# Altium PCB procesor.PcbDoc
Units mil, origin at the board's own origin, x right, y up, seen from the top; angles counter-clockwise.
Board outline 6000 x 4000 mil, 2 copper layers (Top Layer, Bottom Layer); 49 components, 70 nets, 266 pads, 119 vias.
Unrouted connection lines stored in the file: 1.
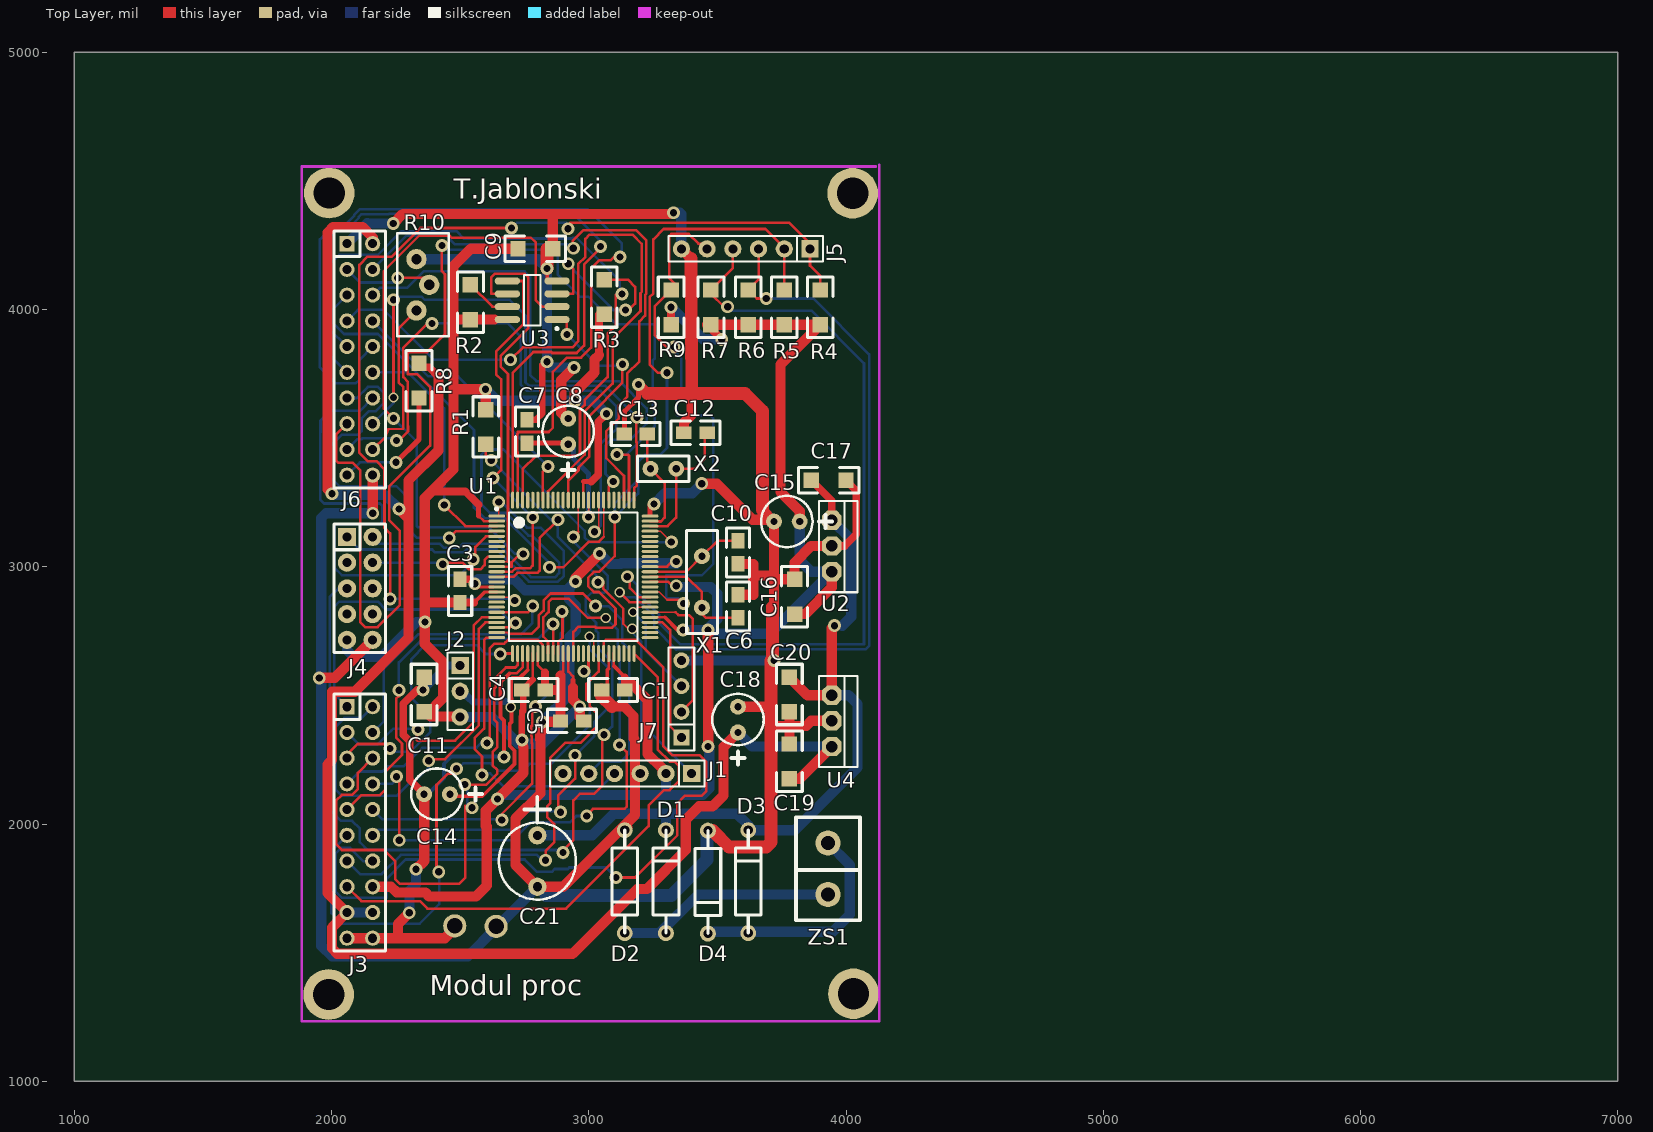
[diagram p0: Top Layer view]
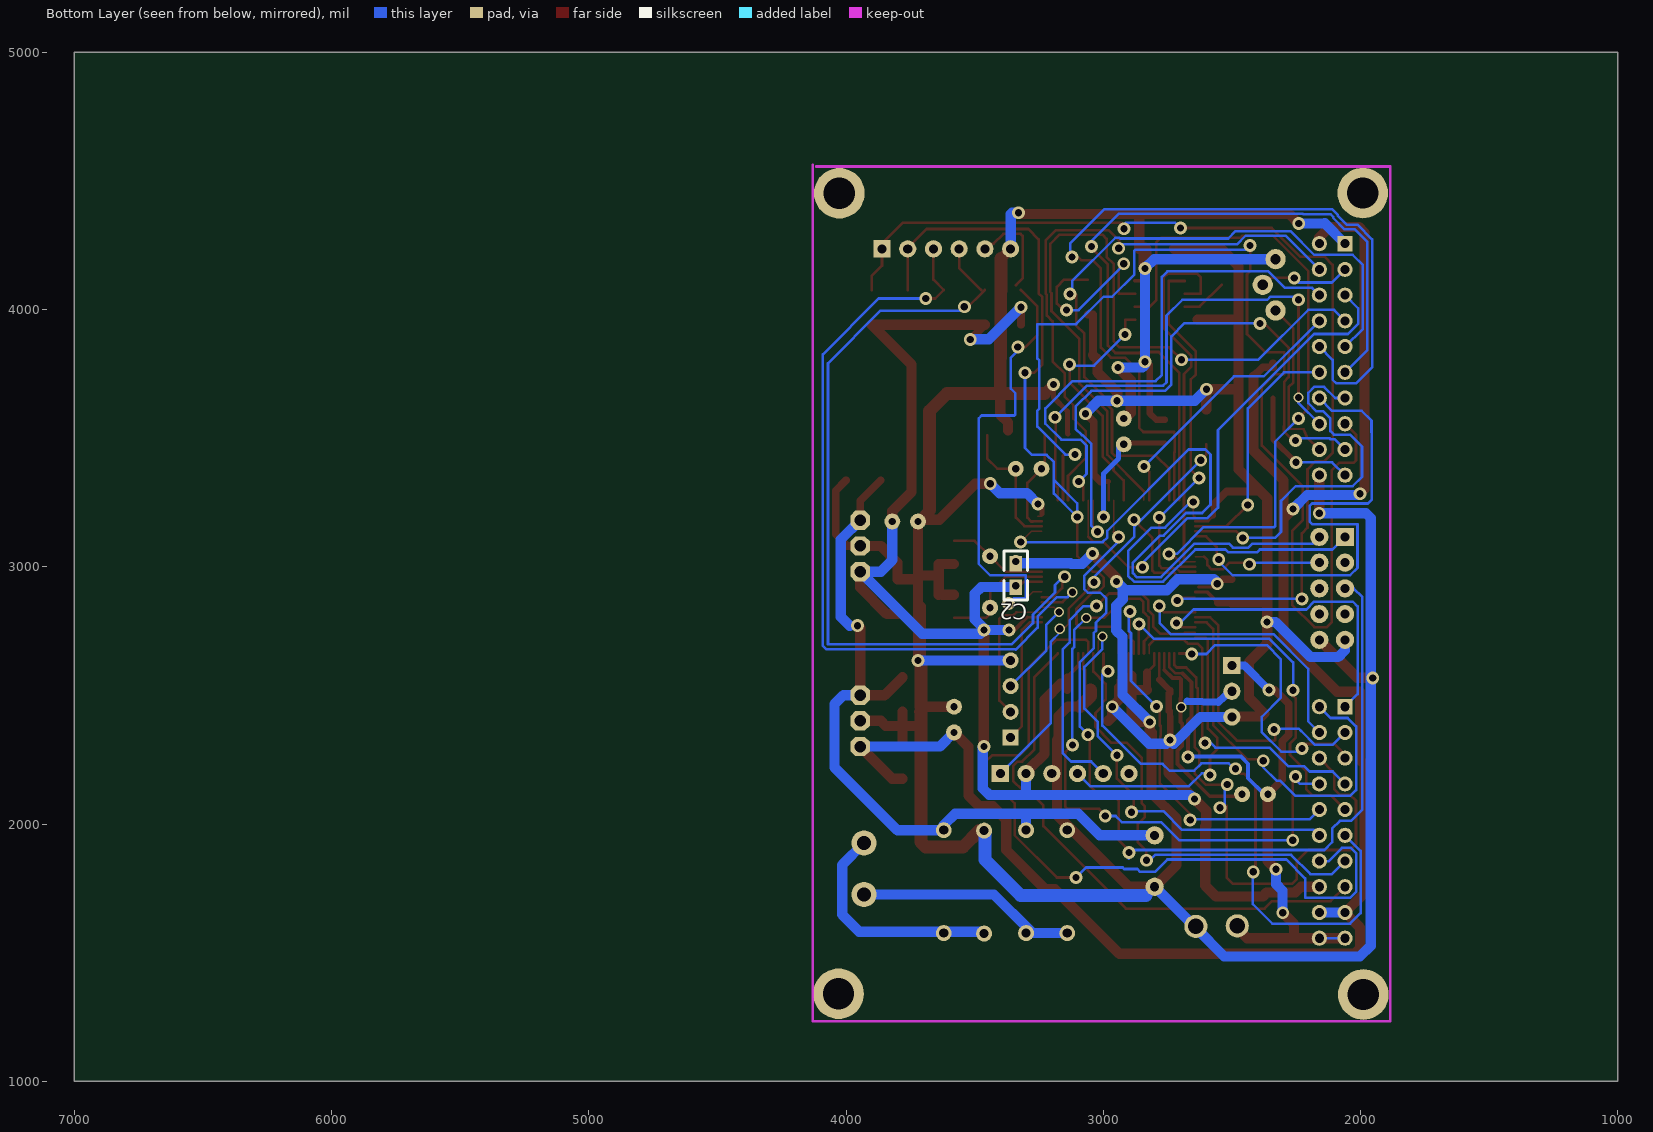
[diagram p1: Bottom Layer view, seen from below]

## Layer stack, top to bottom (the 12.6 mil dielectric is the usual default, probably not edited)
Top Layer: signal copper 1.4
Dielectric: dielectric 12.6, FR-4, Dk 4.8
Bottom Layer: signal copper 1.4

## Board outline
1000,1000 7000,1000 7000,5000 1000,5000

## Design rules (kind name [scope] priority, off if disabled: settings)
Clearance [All] p1: gap=8
PolygonConnect [All] p1: connectstyle=Relief reliefconductorwidth=10 reliefentries=4 polygonreliefangle="90 Angle"
RoomDefinition procesor [InComponentClass('procesor')] p1: confinementstyle=ConfineIn formatcopy=TRUE lockcomponents=FALSE outline 0,0 2000,0 2000,1000 0,1000
RoutingTopology [All] p1: topology=Starburst
RoutingVias [All] p1: holewidth=28 width=50 viastyle="Through Hole" minholewidth=28 minwidth=50 maxholewidth=28 maxwidth=50
SMDNeckDown [All] p1: percent=50.000
SilkscreenOverComponentPads [All] p1: minsilkscreentomaskgap=10
SolderMaskExpansion [All] p1: expansion=4
Width +3,3V [InNet('+3,3V')] p1: maxlimit=40 minlimit=40 preferedwidth=40
Width GND [InNet('GND')] p2: maxlimit=40 minlimit=40 preferedwidth=40
Width +5V [InNet('+5V')] p3: maxlimit=40 minlimit=40 preferedwidth=40
Width ALL [All] p4: maxlimit=10 minlimit=10 preferedwidth=10
26 further rules are at their usual default settings.

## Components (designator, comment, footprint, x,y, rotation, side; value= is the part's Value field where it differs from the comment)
C1 "100n" 0805 3140,2521 r180 top
C2 "100n" 0805 3340,2921 r90 bottom
C3 "100n" 0805 2500,2861 r90 top
C4 "100n" 0805 2740,2521 r0 top
C5 "100n" 0805 2980,2401 r180 top
C6 "22p" 0805 3580,2801 r90 top
C7 "100n" 0805 2760,3481 r90 top
C8 "10u" RB.1/.2 2920,3376 r270 top
C9 "100n" 1206 2860,4236 r180 top
C10 "22p" 0805 3580,3101 r270 top
C11 "100n" 1206 2360,2436 r90 top
C12 "22p" 0805 3460,3521 r180 top
C13 "22p" 0805 3227.29,3516.29 r180 top
C14 "10u" RB.1/.2 2560,2116 r0 top
C15 "10u" RB.1/.2 3920,3176 r0 top
C16 "100n" 1206 3800,2816 r90 top
C17 "100n" 1206 4000,3336 r180 top
C18 "10u" RB.1/.2 3580,2256 r270 top
C19 "100n" 1206 3780,2176 r90 top
C20 "100n" 1206 3780,2436 r90 top
C21 "1000u" RB.2/.3 2800,1956 r270 top
D1 "" DIODE0.4 3300,1576 r90 top
D2 "" DIODE0.4 3140,1976 r270 top
D3 "" DIODE0.4 3620,1576 r90 top
D4 "" DIODE0.4 3463.19,1974.15 r270 top
J1 "ICSP" SIP6 3400,2196 r180 top
J2 "CON3" SIP3 2500,2616 r270 top
J3 "analog" IDC20 2060,2456 r270 top
J4 "SD" IDC10 2060,3116 r270 top
J5 "CON6" SIP6 3860,4236 r180 top
J6 "lcd" IDC20 2060,4256 r270 top
J7 "CON4" SIP4 3360,2336 r90 top
R1 "4K7" 1206 2600,3476 r90 top
R2 "2k2" 1206 2540,4096 r270 top
R3 "2k2" 1206 3060,4116 r270 top
R4 "4K7" 1206 3900,4076 r270 top
R5 "4K7" 1206 3760,4076 r270 top
R6 "4K7" 1206 3620,4076 r270 top
R7 "4K7" 1206 3475,4076 r270 top
R8 "0R" 1206 2340,3656 r90 top
R9 "4K7" 1206 3320,4076 r270 top
R10 "RPot" PR 2380,4096 r90 top
U1 "PIC32MX795F512L-80I/PT" TQFP100 2940,2961 r0 top
U2 "LM2937" 78XXST 3960,3156 r270 top
U3 "25LC256-I/SN" SOIC127P600-8M 2780,4036 r180 top
U4 "LM2937" 78XXST 3960,2476 r270 top
X1 "8MHz" XTAL1 3440,2841 r90 top
X2 "8MHz" RAD0.1 3340,3381 r180 top
ZS1 "" ZLSRUB2-1 3960,1796 r90 top

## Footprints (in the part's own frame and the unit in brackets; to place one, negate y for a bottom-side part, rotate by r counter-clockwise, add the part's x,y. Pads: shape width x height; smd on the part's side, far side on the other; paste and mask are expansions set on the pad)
78XXST [mil]
  oct 75x75 hole 45: 1(-25,-15) 2(75,-15) 3(175,-15)
  silkscreen extent -100,-65 255,85
0805 [mil]
  rect 60x50 smd: 1(0,0) 2(90,0)
  silkscreen extent -50,-45 140,45
1206 [mil]
  rect 60x60 smd: 1(0,0) 2(135,0)
  silkscreen extent -50,-50 185,50
DIODE0.4 [mil]
  round 62 hole 35.43: A(0,0) K(400,0)
  silkscreen extent 0,-50 400,50
IDC10 [mm]
  rect 1.8x1.8 hole 0.9: 1(0,0)
  round 1.8 hole 0.9: 2(0,2.54) 3(2.54,0) 4(2.54,2.54) 5(5.08,0) 6(5.08,2.54) 7(7.62,0) 8(7.62,2.54) 9(10.16,0) 10(10.16,2.54)
  silkscreen extent -1.27,-1.27 11.43,3.81
IDC20 [mm]
  rect 1.5x1.5 hole 0.9: 1(0,0)
  round 1.5 hole 0.9: 2(0,2.54) 3(2.54,0) 4(2.54,2.54) 5(5.08,0) 6(5.08,2.54) 7(7.62,0) 8(7.62,2.54) 9(10.16,0) 10(10.16,2.54) 11(12.7,0) 12(12.7,2.54) 13(15.24,0) 14(15.24,2.54) 15(17.78,0) 16(17.78,2.54) 17(20.32,0) 18(20.32,2.54) 19(22.86,0) 20(22.86,2.54)
  silkscreen extent -1.27,-1.27 24.13,3.81
PR [mil]
  round 79 hole 40: 1(-100,50) 2(100,50) 3(0,0)
  silkscreen extent -200,-75 200,125
RAD0.1 [mil]
  round 62 hole 28: 1(0,0) 2(100,0)
  silkscreen extent -50,-50 150,50
RB.1/.2 [mil]
  round 62 hole 28: 1(-100,0) 2(-200,0)
  silkscreen extent -250,-100 25,100
RB.2/.3 [mm]
  round 1.8 hole 0.9: 1(0,0) 2(5.08,0)
  silkscreen extent -3.81,-3.81 6.35,3.81
SIP3 [mm]
  rect 1.7x1.7 hole 0.9: 1(0,0)
  round 1.7 hole 0.9: 2(2.54,0) 3(5.08,0)
  silkscreen extent -1.27,-1.27 6.35,1.27
SIP4 [mil]
  rect 62x62 hole 35.43: 1(0,0)
  round 62 hole 35.43: 2(100,0) 3(200,0) 4(300,0)
  silkscreen extent -50,-50 350,50
SIP6 [mm]
  rect 1.7x1.7 hole 0.9: 1(0,0)
  round 1.7 hole 0.9: 2(2.54,0) 3(5.08,0) 4(7.62,0) 5(10.16,0) 6(12.7,0)
  silkscreen extent -1.27,-1.27 13.97,1.27
SOIC127P600-8M [mm] "SOIC, 8-Leads, Body 4.9x3.9mm, Pitch 1.27mm, IPC Low Density"
  oval 2.5x0.7 smd: 1(-2.45,1.905) 2(-2.45,0.635) 3(-2.45,-0.635) 4(-2.45,-1.905) 5(2.45,-1.905) 6(2.45,-0.635) 7(2.45,0.635) 8(2.45,1.905)
  silkscreen extent -2.58,-2.5 0.8,2.93, body extent -2,-2.5 2,2.5, height 1.75
TQFP100 [mm]
  oval 1.65x0.3 smd: 1(-7.575,6) 2(-7.575,5.5) 3(-7.575,5) 4(-7.575,4.5) 5(-7.575,4) 6(-7.575,3.5) 7(-7.575,3) 8(-7.575,2.5) 9(-7.575,2) 10(-7.575,1.5) 11(-7.575,1) 12(-7.575,0.5) 13(-7.575,0) 14(-7.575,-0.5) 15(-7.575,-1) 16(-7.575,-1.5) 17(-7.575,-2) 18(-7.575,-2.5) 19(-7.575,-3) 20(-7.575,-3.5) 21(-7.575,-4) 22(-7.575,-4.5) 23(-7.575,-5) 24(-7.575,-5.5) 25(-7.575,-6) 51(7.575,-6) 52(7.575,-5.5) 53(7.575,-5) 54(7.575,-4.5) 55(7.575,-4) 56(7.575,-3.5) 57(7.575,-3) 58(7.575,-2.5) 59(7.575,-2) 60(7.575,-1.5) 61(7.575,-1) 62(7.575,-0.5) 63(7.575,0) 64(7.575,0.5) 65(7.575,1) 66(7.575,1.5) 67(7.575,2) 68(7.575,2.5) 69(7.575,3) 70(7.575,3.5) 71(7.575,4) 72(7.575,4.5) 73(7.575,5) 74(7.575,5.5) 75(7.575,6)
  oval 0.3x1.65 smd: 26(-6,-7.575) 27(-5.5,-7.575) 28(-5,-7.575) 29(-4.5,-7.575) 30(-4,-7.575) 31(-3.5,-7.575) 32(-3,-7.575) 33(-2.5,-7.575) 34(-2,-7.575) 35(-1.5,-7.575) 36(-1,-7.575) 37(-0.5,-7.575) 38(0,-7.575) 39(0.5,-7.575) 40(1,-7.575) 41(1.5,-7.575) 42(2,-7.575) 43(2.5,-7.575) 44(3,-7.575) 45(3.5,-7.575) 46(4,-7.575) 47(4.5,-7.575) 48(5,-7.575) 49(5.5,-7.575) 50(6,-7.575) 76(6,7.575) 77(5.5,7.575) 78(5,7.575) 79(4.5,7.575) 80(4,7.575) 81(3.5,7.575) 82(3,7.575) 83(2.5,7.575) 84(2,7.575) 85(1.5,7.575) 86(1,7.575) 87(0.5,7.575) 88(0,7.575) 89(-0.5,7.575) 90(-1,7.575) 91(-1.5,7.575) 92(-2,7.575) 93(-2.5,7.575) 94(-3,7.575) 95(-3.5,7.575) 96(-4,7.575) 97(-4.5,7.575) 98(-5,7.575) 99(-5.5,7.575) 100(-6,7.575)
  silkscreen extent -7.7,-6.35 6.35,6.82, body extent -7,-7 7,7, height 1.2
XTAL1 [mil]
  round 62 hole 28: 1(0,0) 2(200,0)
  silkscreen extent -100,-60 300,60
ZLSRUB2-1 [mil]
  round 98 hole 55: 1(-70,30) 2(130,30)
  silkscreen extent -170,-95 230,155

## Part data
C1 C2 C3 C4 C5 C6 C7 C10 C11 C12 C13 C16 C17 C19 C20: library part CAP, "Capacitor"
C8 C14 C15 C18 C21: library part ELECTRO2, "Electrolytic Capacitor"
C9: library part Cap, "Capacitor"
D1 D2 D3 D4: library part DIODE, "Diode"
J1: library part CON6, "Connector"
J2 J5 J7: "Connector"
J3 J6: library part 20PIN
J4: library part CON10, "Connector"
R1 R4 R5 R6 R7 R8 R9: library part RES2
R2 R3: library part Res2, "Resistor"
R10: "Potentiometer"
U1: "32-Bit Flash Microcontroller with USB, 85 IOs, 256KB Program Memory, 100-pin TQFP"
U2 U4: library part 78XX
U3: "256K SPI Bus Serial EEPROM, 8-Pin SOIC, Industrial Temperature"
X1 X2: library part CRYSTAL, "Crystal"
ZS1: library part ZLSRUB

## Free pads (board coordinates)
  round 90 hole 60: 0(2479,1604) 0(2640,1602)
  round 196.85 hole 122.05: 0(4029,1340) 1(1989,1337) 2(4026,4452) 3(1991,4453)

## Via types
v1: diameter 50, hole 28, Top Layer to Bottom Layer, 112 vias
v2: diameter 40, hole 28, Top Layer to Bottom Layer, 7 vias

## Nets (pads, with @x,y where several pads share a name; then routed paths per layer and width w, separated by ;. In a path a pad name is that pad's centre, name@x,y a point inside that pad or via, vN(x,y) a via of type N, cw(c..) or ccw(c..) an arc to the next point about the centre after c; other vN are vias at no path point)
+3,3V: C1.1 C2.1 C3.1 C4.1 C5.1 C9.2 C11.1 C15.1 C16.1 J1.2 J2.3 J3.16 J4.9 R1.2 R2.2 R3.2 R4.2 R5.2 R6.2 R7.2 R9.2 U1.2 U1.16 U1.30 U1.37 U1.46 U1.55 U1.62 U1.86 U2.3 U3.8 | length 13055.7
  Top Layer w5.91: 2555,2861 2595,2901 2595.94,2901.94 ; U1.46 3097.48,2614 3165.24,2546.24
  Top Layer w10: 2572,3198 2592.46,3177.54 U1.2 ; 2595.94,2901.94 U1.16 ; 2782.52,2561.52 U1.30 ; U1.37 2920.32,2592.35 2939,2573.67 2939,2560 ; U1.86 2979.37,3331 ; 3097.48,2613.52 U1.46 ; U1.55 3295.65,2803.52 ; U1.62 3309.69,2941.31 v1@3340,2911
  Top Layer w15: 2555,2861 2595,2901 ; 3097.48,2613.52 3140,2571 ; 3295.65,2803.52 v1@3345.17,2754
  Top Layer w20: 2572,3198 2572,3241 ; 2939,2530 2939,2560 ; 2979.37,3331 3010,3331
  Top Layer w25: v1@2740,2317.11 v1(2740,2326) 2740,2417.5 ; C4.1 2740,2508.5 2744.62,2508.5 2744.62,2437.7 ; 2740.5,2417.5 2740.5,2437.7 ; C4.1@2751,2530 2782.52,2561.52
  Top Layer w30: 2389,3293 2520,3293 2572,3241 ; C3.1 2555,2861 ; 3010,3331 3037,3358 3037,3563 v1@3064,3590 ; 3040,3823 3040,3981 R3.2 ; C1.1 3140,2571 ; R9.2 v1(3320,4009) ; R7.2@3460,3941 3467.5,3933.5 v1(3517,3884) ; C16.1@3799,2815 C16.1
  Top Layer w40: J3.16 2231.33,1756 2253.33,1734 2364,1734 2380,1718 2561,1718 2603.52,1760.52 2603.52,1989 2600,1992.52 2600,2052 v1(2645,2097) 2746.5,2198.5 2746.5,2299.7 2744,2302.2 v1@2744,2303.67 ; 2365,2861 C3.1 ; 2475,3961 R2.2 2633,3961 ; 2477,3690 v1(2599,3690) 2599,3612 R1.2 ; J2.3@2492,2418 2385,2418 2373.5,2429.5 2433,2489 2433,2630 2362,2701 2362,2785 2362,3266 2389,3293 2474,3378 2474,4168 2542,4236 C9.2 ; 2939,2530 2939,2482 v1(2965,2456) 2965,2416 C5.1 ; v1(2946,3645) 2946,3679 3022,3755 3022,3805 3040,3823 ; v1@3064,3590 v1(3069,3595) ; 3165.24,2546.24 3228,2483.48 3228,2273 3286.93,2214.07 J1.2@3286.93,2196 ; R7.2@3460,3941 R7.2 R6.2 R5.2 R4.2 3745,3786 3745,3291 3820,3216 C15.1 ; 3462,2711 3462,2754 v1@3462,2756 ; v1@3464,2296 3464,2301 v1(3464,2754) v1@3464,2756 ; C16.1 3841,2816 3945,2920 U2.3
  Bottom Layer w40: J4.9 2060,2676 2087,2649 2194,2649 2330,2785 v1(2363,2785) ; J2.3 2622.14,2416 2726.07,2312.07 v1@2726.14,2312 ; v1(2599,3690) 2644,3645 v1(2946,3645) 3019,3645 v1(3069,3595) ; v1(2645,2097) 2647,2097 2662.96,2112.96 3300,2112.96 ; v1(2740,2326) 2754,2312 2821,2312 v1(2965,2456) ; J1.2 3300,2112.96 ; v1(3320,4009) 3445,3884 v1(3517,3884) ; C2.1 3474,2921 3499,2896 3499,2800 ; v1(3366,2754) v1(3464,2754) ; v1@3462,2759 3499,2796 ; v1(3463,2301) 3468,2296 3468,2138 3442.96,2112.96 3300,2112.96 ; v1@3464,2756 v1@3464.5,2756.5 ; v1@3467.55,2757.75 3465.55,2755.64 3465,2755.06 v1(3464,2754) ; C15.1 3820,3026 3865,2981 U2.3 3704,2740 3478,2740 v1(3464,2754)
  other v1: 3340,2926
+5V: C18.1 C19.1 J3.17 J3.18 J6.2 R8.2 U4.3 | length 7026.5
  Top Layer w30: R8.2 2340,3776 2379.78,3776 2416,3739.78
  Top Layer w40: v1(2002,3284) 1984.47,3301.53 1984.47,4299.47 2006,4321 2119,4321 2160,4280 J6.2 ; v1(2262,3225) 2299,3188 ; 2416,3739.78 2416,3452.3 2299,3335.3 2299,3225 2299,3188 ; C18.1 3524.1,2300.1 3524.1,2111.31 3481.41,2068.61 3429.61,2068.61 3377,2016 3377,1899 3225,1747 3188,1747 2937,1496 2022,1496 2002,1516 2002,1598 J3.17 1984.47,1731.53 1984.47,2231.53 2002,2249.06 2002,2514 2090,2514 2299,2723 2299,3188 ; C19.1 3820,2176 U4.3
  Bottom Layer w40: v1(2002,3284) 2007,3279 2208,3279 v1(2262,3225) ; J3.17 J3.18 ; C18.1 3635,2301 U4.3
AN1: J3.1 U1.23 | length 1221.8
  Top Layer w5.91: 2695.15,2764.15 v1@2708,2777
  Top Layer w10: U1.23 2695.15,2764.15
  Bottom Layer w10: J3.1 2011,2505 2011,2845.43 2030,2864.43 2180.06,2864.43 2210.5,2834 2649,2834 v1@2707,2776
  other v1: 2715,2781
AN2: J3.2 U1.22 | length 1590.5
  Top Layer w10: v1@2378,2235 v1(2378,2246) ; v1@2378,2237 v1(2378,2246) ; U1.22 2598,2783.83 2572.91,2758.74 2572.91,2383.91 2441,2252 2404,2252 2403,2251 2383,2251 v1(2378,2246)
  Bottom Layer w10: J3.2 2116,2412 2050,2412 2017,2379 2017,2132 2040,2109 2253,2109 2312.26,2168.26 2326.26,2168.26 2378,2220 v1(2378,2246)
AN3: J3.3 U1.21 | length 1094.1
  Top Layer w10: v1(2336.46,2367.46) 2332,2363 2332,2326.53 2334.53,2324 2480.04,2324 2553.6,2397.56 2553.6,2773.12 2584,2803.52 U1.21
  Bottom Layer w10: J3.3 2108,2308 2177,2308 2229.6,2360.6 ; 2231,2362 2240,2371 2332.93,2371 v1(2336.46,2367.46)
AN4: J3.4 U1.20 | length 1159.5
  Top Layer w10: U1.20 2764.2,2823.2 2782,2841 v1(2782,2848)
  Bottom Layer w10: J3.4 2203,2399 2203,2603 2338,2738 2738,2738 2780,2780 2780,2848 2780,2850 v1@2771,2859 ; v1@2782,2841 v1(2782,2848)
AN5: J3.5 U1.26 | length 1115.3
  Top Layer w10: J3.5 2060,2270 2101,2311 v1@2226,2311 ; v1(2656,2661) 2657.77,2662.77 U1.26
  Bottom Layer w10: v1@2242,2281 2308,2281 2383,2356 2383,2417 2310,2490 2310,2641 2364,2695 2565,2695 2599,2661 v1(2656,2661)
  other v1: 2227,2293
AN6: J3.6 U1.27 | length 2125.4
  Top Layer w10: J3.6 2102.53,2198.53 2102.53,2135.53 2080,2113 2040,2113 2017.47,2090.47 2017.47,1921.53 2040,1899 2204,1899 2247,1856 2247,1787 2267,1767 2495,1767 2520,1792 2520,2063 2520,2070 ; v1@2518,2134 v1(2518,2154) ; v1@2537,2154 2539,2152 2601.01,2152 2644.61,2195.6 2644.61,2209.39 2626,2228 2626,2280 2644.61,2298.61 2644.61,2393.53 2633,2405.14 2633,2527 2639,2533 2639,2570 2677.5,2608.5 2714.5,2608.5 2723.46,2617.46 U1.27
  Bottom Layer w10: v1@2518,2135 v1(2518,2154) 2527,2145 v1@2527,2070 ; v1@2527.5,2144.5 v1@2537,2154
  other v1: 2546,2063
AN7: J3.7 U1.32 | length 1253.9
  Top Layer w5.91: U1.32 2821.89,2696
  Top Layer w10: v1(2604,2315) 2615,2326 2615,2682 2634,2701 2671,2701 2675.87,2705.87 2676.18,2705.87 2687.25,2716.95 2687.25,2717 2800.89,2717 2821.89,2696
  Bottom Layer w10: J3.7 2108,2204 2198,2204 2219,2225 2281,2225 2353,2297 2564,2297 2593,2326 v1(2604,2315)
AN8: J3.8 U1.33 | length 2555.8
  Top Layer w10: v1(2253,2184) 2263,2174 v1(2263,1937) ; U1.33 2841.57,2710 2823,2728.57 2823,2802.8 2844,2823.8 2844,2863.28 2856.72,2876 2921,2876 2996,2801 v2(3066,2801) ; v1(2992,2031) 2992,2035 3016,2059 3139,2059 3147,2067 3147,2280 v1(3120,2307)
  Bottom Layer w10: J3.8 2235,2156 2258,2179 v1@2268,2189 ; v1(2263,1937) 2705,1937 2775,2007 2928,2007 2952,2031 v1(2992,2031) ; v2(3066,2801) 3113,2754 3113,2687.48 3120,2680.48 v1(3120,2307)
AN9: J3.9 U1.34 | length 1495.7
  Top Layer w10: J3.9 2115,2111 2186,2111 2211,2136 2211,2206 2274,2269 2274,2312.4 2251,2335.4 2251,2487 v1@2262,2498 ; v1@2254,2506 v1@2262,2498 ; v1@2262,2509 v1@2262,2498 ; v1@2264,2496 v1@2262,2498 ; v1(2861,2778) 2861.26,2777.74 U1.34
  Bottom Layer w10: v1(2262.14,2520.14) 2262.14,2628.14 2354,2720 2803,2720 v1(2861,2778)
AN10: J3.10 U1.35 | length 1595.3
  Top Layer w10: v1@2646.5,2024.5 2650,2028 2779.5,2157.5 2779.5,2313.37 2778,2314.87 2778,2341.74 2777,2342.74 2777,2381.26 ; 2781,2381.26 2781,2445 v1(2792.68,2456.68) ; U1.35 2880.94,2707 2898,2724.06 2898,2824 v1(2896,2826)
  Bottom Layer w10: J3.10 2198,2018 2602,2018 ; 2605,2018 2660,2018 v1(2662,2016) ; v1(2792.68,2456.68) 2892,2556 2892,2741.67 2900,2749.67 2900,2822 v1(2896,2826)
AN11: J3.11 U1.41 | length 2233.1
  Top Layer w10: v1@2408,1814 2408,2152 2451,2195 2466,2195 v1(2486,2215) ; v1@2999.06,2600.94 U1.41
  Bottom Layer w10: J3.11 1999,1895 1999,1654 2040,1613 2343,1613 2418,1688 v1@2418,1814 ; v1@2490,2214 2512,2236 2618,2236 2647,2207 2742,2207 2769,2234 2854,2234 3003,2383 v1@3003,2582 ; v1(2982,2594) v1@2984,2592
  other v1: 2417,1814
AN12: J3.12 U1.42 | length 1638.6
  Top Layer w5.91: v2(3003,2729) 3018.74,2713.26 U1.42
  Top Layer w10: v1(2890,2046) 2881,2055 2881,2110 2947,2176 v1(2947,2267)
  Bottom Layer w10: J3.12 2181,1977 2693,1977 2766,2050 2886,2050 v1(2890,2046) ; v1(2947,2267) 3021,2341 3021,2396.27 3073,2448.27 3073,2611 3003,2681 v2(3003,2729)
AN13: J3.13 U1.43 | length 1818
  Top Layer w10: v1(2832,1859) 2832,1895 2865.5,1928.5 2865.5,2000.5 2838,2028 2838,2068 2850,2080 2850,2257 2909,2316 2969,2316 3001,2348 3001,2349 3015,2363 3015.38,2363 3030,2377.62 3030,2431 3003,2458 3003,2471.74 2991,2483.74 2991,2545 3038.43,2592.43 U1.43
  Bottom Layer w10: J3.13 2111,1805 2195,1805 2270,1880 2798,1880 2825.5,1852.5 v1@2832,1846
AN14: J3.14 U1.44 | length 3071.7
  Top Layer w10: U1.44 3058.11,2708 3066.11,2716 3183,2716 3290,2609 3290,2302 3324,2268 3431,2268 3457,2242 3457,2128 3438,2109 3373,2109 3344,2080 3344,1956 3180,1792 v1(3106,1792)
  Bottom Layer w10: J3.14 2123,1856 2072,1907 2037,1907 2017,1887 2017,1736 2040,1713 2215,1713 2215,1789 2288,1862 2751,1862 2799,1814 2856.54,1814 2867.54,1825 2918.46,1825 2924.46,1831 3067,1831 v1(3106,1792)
CLK0: C6.1 U1.63 X1.1 | length 457.8
  Top Layer w10: U1.63 3380,2961 3440,2901 X1.1 3440,2816 3455,2801 C6.1
CLK1: C10.1 U1.64 X1.2 | length 391.6
  Top Layer w10: U1.64 3379.69,2980.69 X1.2 3500,3101 C10.1
CLKT0: C12.1 U1.73 X2.1 | length 529.1
  Top Layer w10: U1.73 3306.85,3157.85 3340,3191 X2.1 3411,3381 3451,3421 C12.1@3451,3512
  Bottom Layer w10: X2.1@3323,3376 X2.1@3323,3381
CLKT1: C13.1 U1.74 X2.2 | length 417
  Top Layer w10: C13.1 3227.29,3408.71 3240,3396 X2.2 3295,3326 3295,3191 3280,3176 3273.39,3176 3272.63,3176.76 3239.01,3176.76 U1.74
DS1820: J3.15 U1.50 | length 2154.6
  Top Layer w10: J3.15 2116,1700 2344,1700 2373,1671 2912,1671 3233,1992 3233,2072 3293,2132 3314,2132 3350,2168 3350,2225 3332.54,2242.46 3315.54,2242.46 3267.99,2290.01 3267.99,2571 U1.50
EE_CS: U1.89 U3.1 | length 1006.7
  Top Layer w10: U3.1 2915,3961 v1(2915,3903) ; U1.89 2920.32,3335.32 2960,3375 2960,3386 3002,3428 3002,3587 3131,3716 v1(3131,3786.98)
  Bottom Layer w10: v1(2915,3903) 3036,3782 3114,3782 3120.01,3775.99 3131,3765 v1(3131,3786.98)
EE_SCK: U1.10 U3.6 | length 1487
  Top Layer w5.91: U1.10 2686,3020.06
  Top Layer w10: U3.6 2621,4061 2621,4126 2634,4139 2751,4139 2764,4126 2764,3927 2658,3821 2658,3777.05 2686,3749.05 2686,3020.06
EE_SDI: U1.12 U3.5 | length 1447.2
  Top Layer w10: v1(2628,3345) 2659,3376 2659,3729 2640,3748 2640,3837 2746,3943 2746,4111 U3.5 ; U1.12 2702.37,2980.69 2715.69,2994 2771,2994 2782,3005 v1(2782,3191)
  Bottom Layer w10: v1(2628,3345) v1(2782,3191)
EE_SDO: U1.11 U3.2 | length 2611.7
  Top Layer w5.91: v1@2733,3050 v1(2745,3050)
  Top Layer w10: v1(2241,3577) 2203,3615 2203,4149 2341,4287 2458.75,4287 2466.75,4279 2774.8,4279 2794,4259.8 2794,4036 2819,4011 U3.2 ; U1.11 2699.73,3000.37 2699.73,3016.73 v1@2733,3050
  Bottom Layer w10: v1(2241,3577) 2332,3486 2332,3157.85 2336.08,3153.77 2609.97,3153.77 2713.74,3050 v1(2745,3050)
GCS1: J6.15 U1.77 | length 4530.6
  Top Layer w10: J6.15 2017.47,3513.47 2017.47,3413 2025.47,3405 2082,3405 2111,3376 2111,2785 2131,2765 2179,2765 2266,2852 2266,3139 2224,3181 2224,3312.3 2383,3471.3 2383,3699 2334,3748 2297,3748 2297,3834 2371,3834 2441,3904 2441,4137 2429,4149 v1(2429,4249) ; v1(3110,3436) 3153,3436 3156.54,3432.46 U1.77
  Bottom Layer w10: v1(2429,4249) 2446,4232 2876,4232 2879,4229 2879,4136 2965,4050 2998,4050 3105,3943 3256,3943 3256,3809 3248,3801 3248,3615.26 3256,3607.26 3256,3545 3147,3436 v1(3110,3436)
GCS2: J6.16 U1.76 | length 2140.2
  Top Layer w10: v2(2241,3658) v1(2241,4038) ; U1.76 3176.22,3306 3187,3316.78 3187,3483.2 3184.29,3485.91 3184.29,3578.29 v1(3187,3581)
  Bottom Layer w10: J6.16 2241,3637 v2(2241,3658) ; v1(2241,4038) 2252,4049 2351.25,4049 2362.25,4038 2692,4038 2754,3976 2754,3717 2767,3704 3064,3704 v1(3187,3581)
GD0: J6.7 U1.93 | length 2824.8
  Top Layer w5.91: U1.93 2841.57,3293.03
  Top Layer w10: v1(2696,3805) 2744,3853 2936,3853 2959,3876 2959,4177 2986.95,4204.95 2986.95,4275 3002.95,4291 3170.63,4291 3206,4255.63 3206,4068.91 3201,4063.91 3201,3994 3093,3886 3093,3712.11 2984,3603.11 2984,3435.46 2841.57,3293.03
  Bottom Layer w10: J6.7 2103,3999 2203,3999 2397,3805 v1(2696,3805)
GD1: J6.8 U1.94 | length 1055.5
  Top Layer w10: U1.94 2821.89,3369.89 v1(2842,3390)
  Bottom Layer w10: J6.8 2376,3740 2492,3740 v1(2842,3390)
GD2: J6.9 U1.98 | length 2760.1
  Top Layer w10: U1.98 2743.15,3380.15 2794,3431 2954,3431 2966,3443 2966,3610.57 2984,3628.57 2984,3647.93 3073,3736.93 3073,3906 3105,3938 3105,4058 3118,4071 3123,4076 3125,4076 3129,4072 v1(3129,4060)
  Bottom Layer w10: J6.9 1991,3925 1991,4173 2031,4213 2180,4213 2272,4305 2485,4305 2514,4276 2934.74,4276 2937.74,4279 2953,4279 3121,4111 3121,4074 3123,4076 3125,4076 3129,4072 v1(3129,4060)
GD3: J6.10 U1.99 | length 3434.3
  Top Layer w10: U1.99 2723.46,3444.15 2722,3445.62 2722,3516.38 2723.46,3517.85 2723.46,3524 2844,3524 2860,3540 2860,3758 2915,3813 2969.82,3813 3009,3852.18 3009,4159.97 3040.03,4191 3085,4191 3110,4216 3111,4217 3122,4206 v1(3122,4204)
  Bottom Layer w10: J6.10 2108,3804 2108,3727 2094,3713 2017,3713 1955,3775 1955,4273 2012,4330 2054,4330 2087.8,4363.8 2087.8,4367.64 2110.16,4390 2995,4390 3129,4256 3129,4211 v1(3122,4204)
GD4: J6.11 U1.100 | length 2959.6
  Top Layer w10: U1.100 2703.78,3753.99 2784.79,3835 2853.74,3835 2857.74,3831 2953.02,3831 2982,3859.98 2982,4174.54 3046,4238.54 v1(3046,4245)
  Bottom Layer w10: J6.11 1973,3843 1973,4263 2022,4312 2061.46,4312 2105.8,4356.35 2105.8,4360.19 2116.39,4370.77 2120.23,4370.77 ; 2121,4370 2222.26,4370 2224.26,4372 2940,4372 3046,4266 v1(3046,4245)
GD5: J6.12 U1.3 | length 949.9
  Top Layer w10: v1(2438,3239.77) 2519.92,3157.85 U1.3
  Bottom Layer w10: J6.12 2298,3756 2438,3616 v1(2438,3239.77)
GD6: J6.13 U1.4 | length 1462.6
  Top Layer w10: v1(2457.83,3112) 2484,3138.17 U1.4
  Bottom Layer w10: J6.13 2098,3656 2141,3699 2180,3699 2203,3676 2203,3636 2172,3605 2146,3605 2117,3576 2117,3527.47 2103,3513.47 2040,3513.47 1994,3467.47 1994,3349.86 2030.86,3313 2252,3313 2309,3256 2309,3136 2333,3112 v1(2457.83,3112)
GD7: J6.14 U1.5 | length 1956.7
  Top Layer w10: v1(2551,3028) 2558,3028 2559,3029 2559,3077.48 2600,3118.48 U1.5
  Bottom Layer w10: J6.14 2110,3606 1995,3606 1957,3568 1957,3523 1956,3522 1956,3261.47 1971.47,3246 2188,3246 2198,3236 2198,3176 2187,3165 2011.57,3165 2011.57,2995.43 2040,2967 2497,2967 2551,3021 v1(2551,3028)
GE: J6.6 U1.81 | length 2033.6
  Top Layer w5.91: v1@3077.8,3313.8 v1(3095,3331)
  Top Layer w10: U1.81 v1@3077.8,3313.8
  Bottom Layer w10: J6.6 2188,4084 2293.75,4084 2358.25,4148.5 2750.5,4148.5 2772,4127 2772,3746 2796,3722 3119,3722 3225,3616 3225,3556 3163,3494 3088,3494 3065,3471 3065,3361 v1(3095,3331)
GND: C1.2 C2.2 C3.2 C4.2 C5.2 C6.2 C7.2 C8.2 C9.1 C10.2 C12.2 C13.2 C15.2 C16.2 C17.1 C18.2 C19.2 C20.1 C21.2 D2.A D4.A J1.3 J4.10 J5.6 J6.1 J6.20 J7.4 pad.0@2640,1602 R10.2 U1.15 U1.31 U1.36 U1.45 U1.65 U1.75 U2.2 U3.4 U4.2 | length 17808.4
  Top Layer w5.91: U1.75 U1.75@3254,3197.22
  Top Layer w10: U1.31 2802.2,2616.8 2830,2589 ; 2890,2576 2900.63,2586.63 U1.36 ; 3077.8,2603.8 U1.45 ; U1.65 3304.37,3000.37 v1@3335,3031
  Top Layer w12: v1@2565,2921 U1.15@2630,2921
  Top Layer w13.78: v1(2838,4160) 2838,4111 U3.4 ; C9.1@2838,4236 2849,4247 C9.1@2860,4258
  Top Layer w15: C1.2@3072,2535 3072,2598 3077.8,2603.8
  Top Layer w20: 2535,2951 v1@2565,2921 ; C13.2 3139.54,3518.54 3139.54,3604.41 3193,3657.88 v1(3193,3709) ; 3238.23,3206 v1@3238.23,3239.23
  Top Layer w25: C7.2 2794,3571 2819,3596 2819,3785 2831,3797 v1(2838,3797) ; C4.2 C4.2@2852,2521
  Top Layer w30: C3.2 2535,2951 ; C4.2 2830,2589 ; 3709,2436 3720,2436 ; U2.2 3995,3081 4040,3126 4040,3296 C17.1
  Top Layer w40: v1@1960,2568.44 2012.44,2568.44 J4.10 ; v1(2160,3208) J6.20 ; v1(2240,4334) 2277.53,4371.53 2860,4371.53 ; C4.2 2889,2521 2890,2522 ; C9.1 2860,4258 2860,4371.53 ; C5.2@2886,2397 v1(2819,2397) 2819,2363 2811,2355 2811,2328.54 2812.5,2327.04 2812.5,2118.5 2715,2021 2715,1841 C21.2 2900,1756 3130,1986 D2.A@3130.19,1986.19 ; C5.2 2890,2522 ; 2890,2576 2890,2522 ; C8.2@2910,3581 2893,3598 2893,3725 v1(2943,3775) ; v1@2949,2958 v1(3042,3051) ; 3090,2457 3137,2457 3174,2420 3174,2332 3180,2326 3180,2196 J1.3@3180,2191 ; D2.A@3149.81,1986.19 3140,1986.19 D2.A@3130.19,1986.19 ; v1(3193,3709) 3228.04,3673.96 ; J1.3 3200,2191 J1.3@3180,2191 ; v1@3331,4377 3329.5,4375.5 3325.53,4371.53 2860,4371.53 ; J5.6 3398.08,4198.22 ; C12.2@3370,3531 3369.88,3560.88 3400.45,3591.69 3400.13,3673.96 ; v1(3439,3323) 3497,3323 3637.12,3182.88 C15.2@3705,3182.88 ; D4.A D4.A@3481.85,1974.15 ; C18.2 3709,2456 3709,2436 ; C6.2 3624,2891 ; C10.2 3639,3011 3639,2966 ; 3639,2891 3639,2966 ; 3675,3221 C15.2 3720,2971 ; 3709,2311 3709,2366 ; 3709,2381 3780,2381 ; v1@3709,2636 3709,2845 3720,2856 ; v1(3720,2636) 3720,2856 ; C19.2 3780,2381 ; C20.1 3780,2381 ; U4.2 3865,2401 3845,2381 3780,2381 ; U2.2 3865,3081 3800,3016 C16.2 3720,2951 ; D2.A@3130.19,1986.19 3180,2036 J1.3@3180,2191 ; 3639,2966 3715,2966 3720,2971 ; 3720,2856 3720,2951 ; 3720,2951 3720,2971
  Top Layer w50: v1(2838,4160) C9.1@2838,4236 ; C1.2 3050,2497 3090,2457 ; 3228.04,3673.96 3400.13,3673.96 ; 3398.08,4198.22 3400.13,3673.96 ; D4.A@3481.85,1974.15 3545,1911 3690,1911 3709,1930 3709,2311 3709,2381 3709,2436 ; 3675,3221 3675,3606 3607.04,3673.96 3400.13,3673.96 ; 3709,2456 v1@3709,2636
  Bottom Layer w40: J6.1 2139,4335 v1(2240,4334) ; v1(2160,3208) 1978.57,3208 1960,3189.43 1960,2567 1960,1527 2002,1485 2529,1485 2643,1599 C21.2 2834,1722 ; R10.2 2802,4196 v1(2838,4160) v1(2838,3797) ; v1(2557,2934) 2557,2939 2569,2951 2710,2951 2752,2909 2915,2909 2924,2918 ; v1(2819,2397) 2925,2503 2925,2728 2949,2752 2949,2847.95 2924,2872.95 2924,2918 ; v1@2838,3784 2847,3775 v1(2943,3775) ; v1(2949,2943) 2924,2918 ; v1(3042,3051) 3082,3011 3125.05,3011 3128.05,3014 3337,3014 C2.2 ; v1(3254,3244) 3296,3286 3402,3286 v1(3439,3323) ; v1(3329,4376) 3354,4376 3360,4370 J5.6 ; J7.4 v1(3720,2636)
  Bottom Layer w50: 2834,1722 3321,1722 3460,1861 D4.A@3460,1974.15
  other v1: 1952,2567 3340,3021
GRS: J6.4 U1.78 | length 2308.1
  Top Layer w10: v1(2940,4238) 2940,4239 2937,4242 2937,4267 2979,4309 3183,4309 3224,4268 3224,4061.46 3219,4056.46 3219,3976 3197,3954 3197,3798.69 3149,3750.69 3149,3660.55 3116.54,3628.08 3116.54,3575.54 3068,3527 3068,3422.18 3136.85,3353.33 U1.78
  Bottom Layer w10: J6.4 2291,4287 2446,4287 2480,4253 2925,4253 v1(2940,4238)
GRST: J6.17 U1.83 | length 2370.7
  Top Layer w5.91: v1@3038.43,3152.43 U1.83
  Top Layer w10: v1(2252,3491) 2257,3496 2267.38,3496 2297.17,3525.79 2297.17,3546.21 2297,3546.38 2297,3719 2279,3737 2279,3852 2373,3946 v1(2390,3946) ; v1(3022,3136) v1@3038.43,3152.43
  Bottom Layer w10: J6.17 2099.47,3495.47 2117,3495.47 2120.53,3499 2244,3499 v1(2252,3491) ; v1(2390,3946) 2685.51,3946 2735.51,3896 2735.51,3708.49 2760,3684 3046,3684 3107,3623 3107,3536 3083,3512 3080.54,3512 3047,3478.46 3047,3161 v1(3022,3136)
GRW: J6.5 U1.82 | length 1951.7
  Top Layer w5.91: 3058.11,3116 U1.82
  Top Layer w10: v1(2847,2998) 2900.74,2998 3000.74,3098 3040.11,3098 3058.11,3116
  Bottom Layer w10: J6.5 2009,4005 2009,3944.47 2048.47,3905 2180,3905 2553.84,3531.16 2553.84,3229.93 2594.9,3188.87 2672.13,3188.87 2847,3014 v1(2847,2998)
MCLR: J1.1 R1.1 U1.13 | length 2064.2
  Top Layer w10: R1.1 2600,3435 v1(2621,3414) ; U1.13 2708,2961 2723,2976 2800.2,2976 2809,2984.8 2809,3111.64 v1(2880,3182.64) ; v1(3036,2940) 3056,2940 3056,2915 3134,2837 3134,2778.48 3153.48,2759 v2(3169,2759)
  Bottom Layer w10: v1(2621,3414) 2852.36,3182.64 ; v1(2880,3182.64) 2852.36,3182.64 ; v1(3036,2940) 3036,2960 2880,3116 2880,3155 2866.18,3168.82 2852.36,3182.64 ; v2(3169,2759) 3169,2743.48 3203.22,2709.25 3203.22,2392.78 J1.1
NetC17_2: C17.2 C20.2 C21.1 D1.K D3.K U2.1 U4.1 | length 2944.8
  Top Layer w10: v1@3945,2761 v1(3955,2771)
  Top Layer w30: C17.2 3945,3256 U2.1
  Top Layer w40: C20.2 3850,2501 U4.1@3925,2501 ; U4.1 v1@3945,2761
  Bottom Layer w10: v1(3955,2771) 3985,2771
  Bottom Layer w40: C21.1 3013,1956 3097,2040 3300,2040 ; D1.K 3300,2040 ; D3.K 3800,1976 4045,2221 4045,2466 4010,2501 U4.1 ; D3.K@3620,1996 3576,2040 3300,2040 ; U2.1 4020,3106 4020,2806 3985,2771
NetD1_A: D1.A D2.K ZS1.1 | length 857.1
  Bottom Layer w40: D2.K@3130,1576 D2.K D1.A@3270,1576 ; D1.A@3275,1576 3287.5,1588.5 3425,1726 ZS1.1
NetD3_A: D3.A D4.K ZS1.2 | length 881
  Bottom Layer w40: D4.K@3475,1581 3620,1581 3948,1581 4015,1648 4015,1841 ZS1.2
NetJ6_19: J6.19 R8.1 | length 498.6
  Top Layer w20: v1(2251,3406) 2340,3495 R8.1
  Bottom Layer w10: J6.19 2110,3406 v1(2251,3406)
NetJ7_1: J7.1 U1.54 | length 526.5
  Top Layer w10: U1.54 3286.35,2783.83 3316,2754.18 3316,2380 J7.1
NetJ7_2: J7.2 U1.56 | length 556.4
  Top Layer w5.91: U1.56 3337.25,2823.2
  Top Layer w10: 3337.25,2823.2 3348.46,2812 3390,2812 3404,2798 3404,2480 J7.2
NetJ7_3: J7.3 U1.57 | length 439.9
  Top Layer w5.91: v2(3172,2824) 3190.89,2842.89 U1.57
  Bottom Layer w10: v2(3172,2824) 3221.22,2774.78 3221.22,2674.78 J7.3
NetR2_1: R2.1 U3.7 | length 178.8
  Top Layer w10: R2.1 2625,4011 U3.7
NetR3_1: R3.1 U3.3 | length 748.1
  Top Layer w10: U3.3 2939,4061 2939,4159 v1(2920,4178) ; R3.1 3152,4116 3180,4088 3180,4023 3149,3992 3143,3986 v1(3143,3998)
  Bottom Layer w10: v1(2920,4178) 2920,4174.23 3096.23,3998 v1(3143,3998)
PGC2: J1.5 U1.24 | length 1366.1
  Top Layer w5.91: U1.24 2685,2744.46 2689.46,2740
  Top Layer w10: 2689.46,2740 2779,2740 2805,2766 2805,2810.26 2824.74,2830 2824.74,2869.48 2851.26,2896 2977,2896 v1(3026,2847)
  Bottom Layer w10: J1.5 3047,2243 3125,2243 3158,2276 3158,2678.48 3131,2705.48 3131,2792 3076,2847 v1(3026,2847)
PGD2: J1.4 U1.25 | length 1163.8
  Top Layer w10: v1(2585,2191) 2585,2262 2556,2291 2556,2334 2593,2371 2593,2716 2601.78,2724.78 U1.25
  Bottom Layer w10: v1(2585,2191) 2590.63,2196.63 2617,2196.63 2667.68,2145.96 3025.4,2145.96 3026.45,2147 3051,2147 J1.4
SD_CD: J4.5 U1.87 | length 3598.4
  Top Layer w5.91: 2959.69,3135.69 U1.87
  Top Layer w10: v1(2900,1889) 2898,1887 2894,1891 2896,1893 2940,1937 2940,2092 2965,2117 3020,2117 3053,2150 3053,2341 v1(3059,2347) ; v1(2940,3116) 2959.69,3135.69
  Bottom Layer w10: J4.5 2027.13,2916 1993,2881.87 1993,2056 2037,2012 2080,2012 2110,1982 2110,1929 2140,1899 2890,1899 v1(2900,1889) v1@2900,1866 ; v1(2940,3116) 2940,3098.12 3074,2964.12 3074,2913 3060,2899 3011,2899 2988,2876 2988,2823 3028,2783 3028,2750.67 3037,2741.67 3037,2683 3091,2629 3091,2379 v1(3059,2347)
SD_CLK: U1.70
SD_CS: J4.1 U1.1 | length 1425
  Top Layer w5.91: U1.1 2650,3197.22 v1(2650,3252)
  Bottom Layer w10: J4.1 2109,3067 2390.83,3067 2401.83,3056 2513.83,3056 2524.83,3067 2642,3067 2767,2942 2880,2942 2903,2965 2903,3061.25 2812.25,3152 2759.91,3152 2659.92,3252 v1(2650,3252)
SD_DIN: J4.2 U1.72 | length 2450.8
  Top Layer w5.91: U1.72 3278.83,3138.17 v1(3321,3096)
  Bottom Layer w10: J4.2 2186,3090 2419.83,3090 2435.83,3074 2495.83,3074 2511.83,3090 2645,3090 2775,2960 2870,2960 2885,2975 2885,3016 2780,3121 2765.46,3121 2677.52,3208.94 2615.59,3208.94 2583,3241.52 2583,3436 2603,3456 2668,3456 2984,3140 2984,3114 3002,3096 v1(3321,3096)
SD_DO: J4.4 U1.9 | length 532.2
  Top Layer w5.91: 2608.69,3039.74 U1.9
  Top Layer w10: v1(2432,3010) 2438,3016 2509.26,3016 2535.26,2990 2578.95,2990 2594.95,3006 2594.95,3026 2608.69,3039.74
  Bottom Layer w10: J4.4 2430,3016 2432,3014 v1(2432,3010)
SD_SCK: J4.3
SD_WD: J4.6
SD_WE: U1.88
SW1: J5.1 R4.1 U1.17 | length 4009.5
  Top Layer w5.91: U1.17 2699.74,2882.26 2712,2870 v1(2712,2869)
  Top Layer w10: v1(2228,2875) 2228,3130 2206,3152 2206,3379 2174,3411 2140,3411 2108,3443 2108,4174 2140,4206 2234.54,4206 2345.54,4317 v1(2700,4317) ; v1(2919,4314) 2929,4338 3289,4338 ; 3291.07,4337.53 3687.07,4337.53 ; 3693,4338 3778,4338 3860,4256 J5.1 3860,4171 3900,4131 R4.1
  Bottom Layer w10: v1(2228,2875) 2707,2875 2712,2870 v1(2712,2869) ; v1(2700,4317) 2720,4337 2913,4337 2919,4331 v1(2919,4314)
SW2: J5.2 R5.1 U1.38 | length 2951.5
  Top Layer w10: U1.38 2940,2747 2960,2767 3024,2767 3028,2763 3091,2763 3104,2776 3104,2837 3039,2902 3020,2902 2998,2924 2998,2958 3020,2980 3040,2980 3101,3041 v1(3101,3193) ; v1(3304,3754) 3269,3754 3237,3786 3237,4049 3251,4063 3251,4273 3291,4313 3687,4313 3742,4258 J5.2@3760,4258 ; R5.1 J5.2 J5.2@3760,4256
  Bottom Layer w10: v1(3304,3754) 3304,3462 3277,3435 3220,3435 3192,3407 3192,3337 ; 3192,3337 3192,3284 v1(3101,3193) 3101,3246 3192,3337
SW3: J5.3 R6.1 U1.58 | length 3131.8
  Top Layer w10: v2(3120,2901) 3158.43,2862.57 U1.58 ; J5.3@3660,4256 J5.3 3660,4116 R6.1 3653,4043 v1(3690,4043)
  Bottom Layer w10: v2(3120,2901) 3139,2882 3180,2882 3255,2807 3255,2763 3339.89,2678.11 3341.77,2680 4077.46,2680 4090,2692.54 4090,3826 3873,4043 v1(3690,4043)
SW4: J5.4 R7.1 U1.59 | length 3246.2
  Top Layer w10: v1@3145,2956 v1(3150,2961) ; v1@3160,2956 3160,2916.56 3194.3,2882.26 U1.59 ; R7.1@3460,4076 3467.5,4068.5 3532.5,4003.5 v1@3537,3999 ; R7.1 3560,4161 J5.4 J5.4@3560,4256
  Bottom Layer w10: v1(3150,2961) 3145,2956 3150,2956 3160,2956 3187.46,2928.54 3187.46,2900 3273,2814.46 3273,2781 3356,2698 4070,2698 4070,3791 3865,3996 v1@3540,3996
  other v1: 3540,4011
SW5: J5.5 R9.1 U1.60 | length 2154.4
  Top Layer w5.91: U1.60 3274.06,2901.94 3305,2871
  Top Layer w10: 3305,2871 v1@3354,2871 ; R9.1 3256,4012 3256,3901 3303,3854 v1(3332,3854) ; R9.1@3339,4095 3313,4121 3313,4286 3321,4294 3388.47,4294 3426.47,4256 J5.5@3460,4256
  Bottom Layer w10: v1(3332,3854) 3325,3847 3359,3813 3359,3692 3342,3675 3342,3591 ; 3345,3588 3473,3588 3484,3577 3484,3011 3440,2967 3302,2967 3302,2877.11 3347.89,2877.11 v1(3368,2857)
VCAP: C7.1 C8.1 U1.85 | length 556.7
  Top Layer w5.91: v1@2999.06,3194.06 U1.85
  Top Layer w10: C8.1@2920,3481 C8.1@2940,3481 ; v1(2999,3194) v1@2999.06,3194.06
  Top Layer w20: C7.1 C8.1@2920,3481
  Bottom Layer w10: C8.1@2940,3476 C8.1@2940,3481
  Bottom Layer w20: C8.1@2940,3476 2940,3421 2999,3362 v1(2999,3194)
VEE: J6.18 R10.1 | length 655.4
  Top Layer w10: J6.18 2209,3505 2220,3534 2279,3536 2279,3699 2261,3717 2261,3927 R10.1
VO: J6.3 R10.3 | length 375.6
  Top Layer w10: v1(2257.53,4123) 2380,4123 R10.3
  Bottom Layer w10: J6.3 2111,4105 2239.53,4105 v1(2257.53,4123)
VREF+: C14.1 J2.2 U1.29 | length 1032.5
  Top Layer w10: C14.1@2460,2108 C14.1 C14.1@2460,2136 ; 2693,2216 2694,2216 ; 2697,2490.62 2699,2488.62 ; 2699,2562 2704.21,2567.21 ; 2762.83,2598.83 U1.29
  Top Layer w15: C14.1@2460,2108 2586,2108 2694,2216 2711,2233 2711,2285 2693,2303 2693,2390 2697,2394 ; 2697,2490.62 2697,2562 ; 2699,2396 2699,2454 2699,2488.62 ; 2704.21,2567.21 2731.21,2567.21 2762.83,2598.83
  Bottom Layer w10: 2673.41,2477.08 v2@2697,2455
  Bottom Layer w30: J2.2@2503.29,2519.29 2552.66,2473.08 2673.41,2477.08
  other v2: 2697,2454
VREF-: C11.2 C14.2 J2.1 J3.19 J3.20 pad.0@2479,1604 U1.28 | length 2749.1
  Top Layer w10: J3.20 J3.20@2161,1556 ; v1(2356,2521) v1@2355.75,2521 ; v1@2361,2526 2355.88,2521.12 v1@2355.75,2521 ; v1@2670,2259 v1(2670,2260) ; 2691.21,2585.21 2719.21,2585.21 2743.15,2609.15 U1.28 ; v1@2355.75,2521 2355,2521 2340,2506 v1@2355.75,2521
  Top Layer w15: v1(2670,2260) 2670,2403 2657,2416 2657,2551 2691.21,2585.21
  Top Layer w20: v1(2356,2521) v1@2361,2526
  Top Layer w30: 2241,1556 2258,1573 ; v1@2355,2521 2333,2521 2279,2467 2279,2347 2304,2322 2304,2172 C14.2
  Top Layer w40: J3.19 J3.20 2241,1556 2440,1556 pad.0@2478,1594 ; 2258,1573 2258,1611 v1(2302,1655) ; v1(2328,1824) 2360,1856 C14.2
  Bottom Layer w10: J3.19 J3.20 J3.20@2161,1556 ; v1@2286,1671 v1(2302,1655) ; C14.2 C14.2@2375,2116 ; v1@2668,2262 v1(2670,2260)
  Bottom Layer w15: C14.2@2375,2116 2437,2178 2437,2234 2465,2262 v1@2668,2262
  Bottom Layer w30: v1(2356,2521) 2451,2616 J2.1
  Bottom Layer w40: v1@2303,1663 2303,1741 2328,1766 v1(2328,1824)
pads on no net: J1.6 J4.7 J4.8 U1.6 U1.7 U1.8 U1.14 U1.18 U1.19 U1.39 U1.40 U1.47 U1.48 U1.49 U1.51 U1.52 U1.53 U1.61 U1.66 U1.67 U1.68 U1.69 U1.71 U1.79 U1.80 U1.84 U1.90 U1.91 U1.92 U1.95 U1.96 U1.97

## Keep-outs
Keep-Out Layer:
  lines w10: 1885,1233 4130,1233 4130,4562 ; 1885,1239 1885,4556 4115,4556

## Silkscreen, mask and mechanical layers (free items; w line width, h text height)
Top Overlay:
  text "T.Jablonski" at 2476,4430 h78.74
  text "Modul proc" at 2382,1334 h78.74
